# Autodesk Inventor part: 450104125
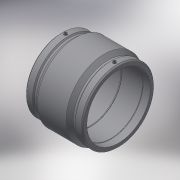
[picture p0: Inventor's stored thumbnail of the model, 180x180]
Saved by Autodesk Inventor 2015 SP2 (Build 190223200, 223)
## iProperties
Created: 2017-06
Part Number: 450104125
Material: Generic
Description: PLASSON COUPLER 125 PN25
Document SubType Name: Modeling
Designer: KIM
Mass: 8622.19 g
Surface Area: 6772.47 cm^2
Volume: 8622.19 cm^3
Density: 1 g/cm^3
Appearance: Default
Author: KIM
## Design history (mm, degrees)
derived "450104.ipt"
feature "Solid1::450104.ipt"
tag "TaggingFeature1"
body "Solid1"
other parameters: "d0" = 173, "d1" = 125, "d2" = 157, "d3" = 85, "d4" = 43.25, "d5" = 141.3, "d7" = 125, "d8" = 168 deg, "d10" = 34, "d11" = 11.33333, "d13" = 173, "d14" = 17.6296, "d15" = 85, "d16" = 85, "d17" = 123.75, "d18" = 125, "d19" = 3.52592, "d20" = 168 deg, "d22" = 147.58, "d23" = 157, "d24" = 143.1526, "d25" = 135 deg, "d26" = 77.85, "d27" = 135 deg, "d29" = 87, "d30" = 15, "d31" = 60.55, "d34" = 5 deg, "d35" = 15, "d39" = 5 deg, "d41" = 4, "d42" = 14, "d43" = 0, "d45" = 4, "d46" = 14, "d47" = 0, "d48" = 3, "d49" = 0, "d50" = 3, "d51" = 0, "d52" = 24.65, "d53" = 6.1625, "d_" = 125, "L_" = 173, "L_1" = 85, "D_" = 157, "A_" = 87, "d_2" = 12
